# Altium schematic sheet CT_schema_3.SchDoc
size 309 x 321 mm
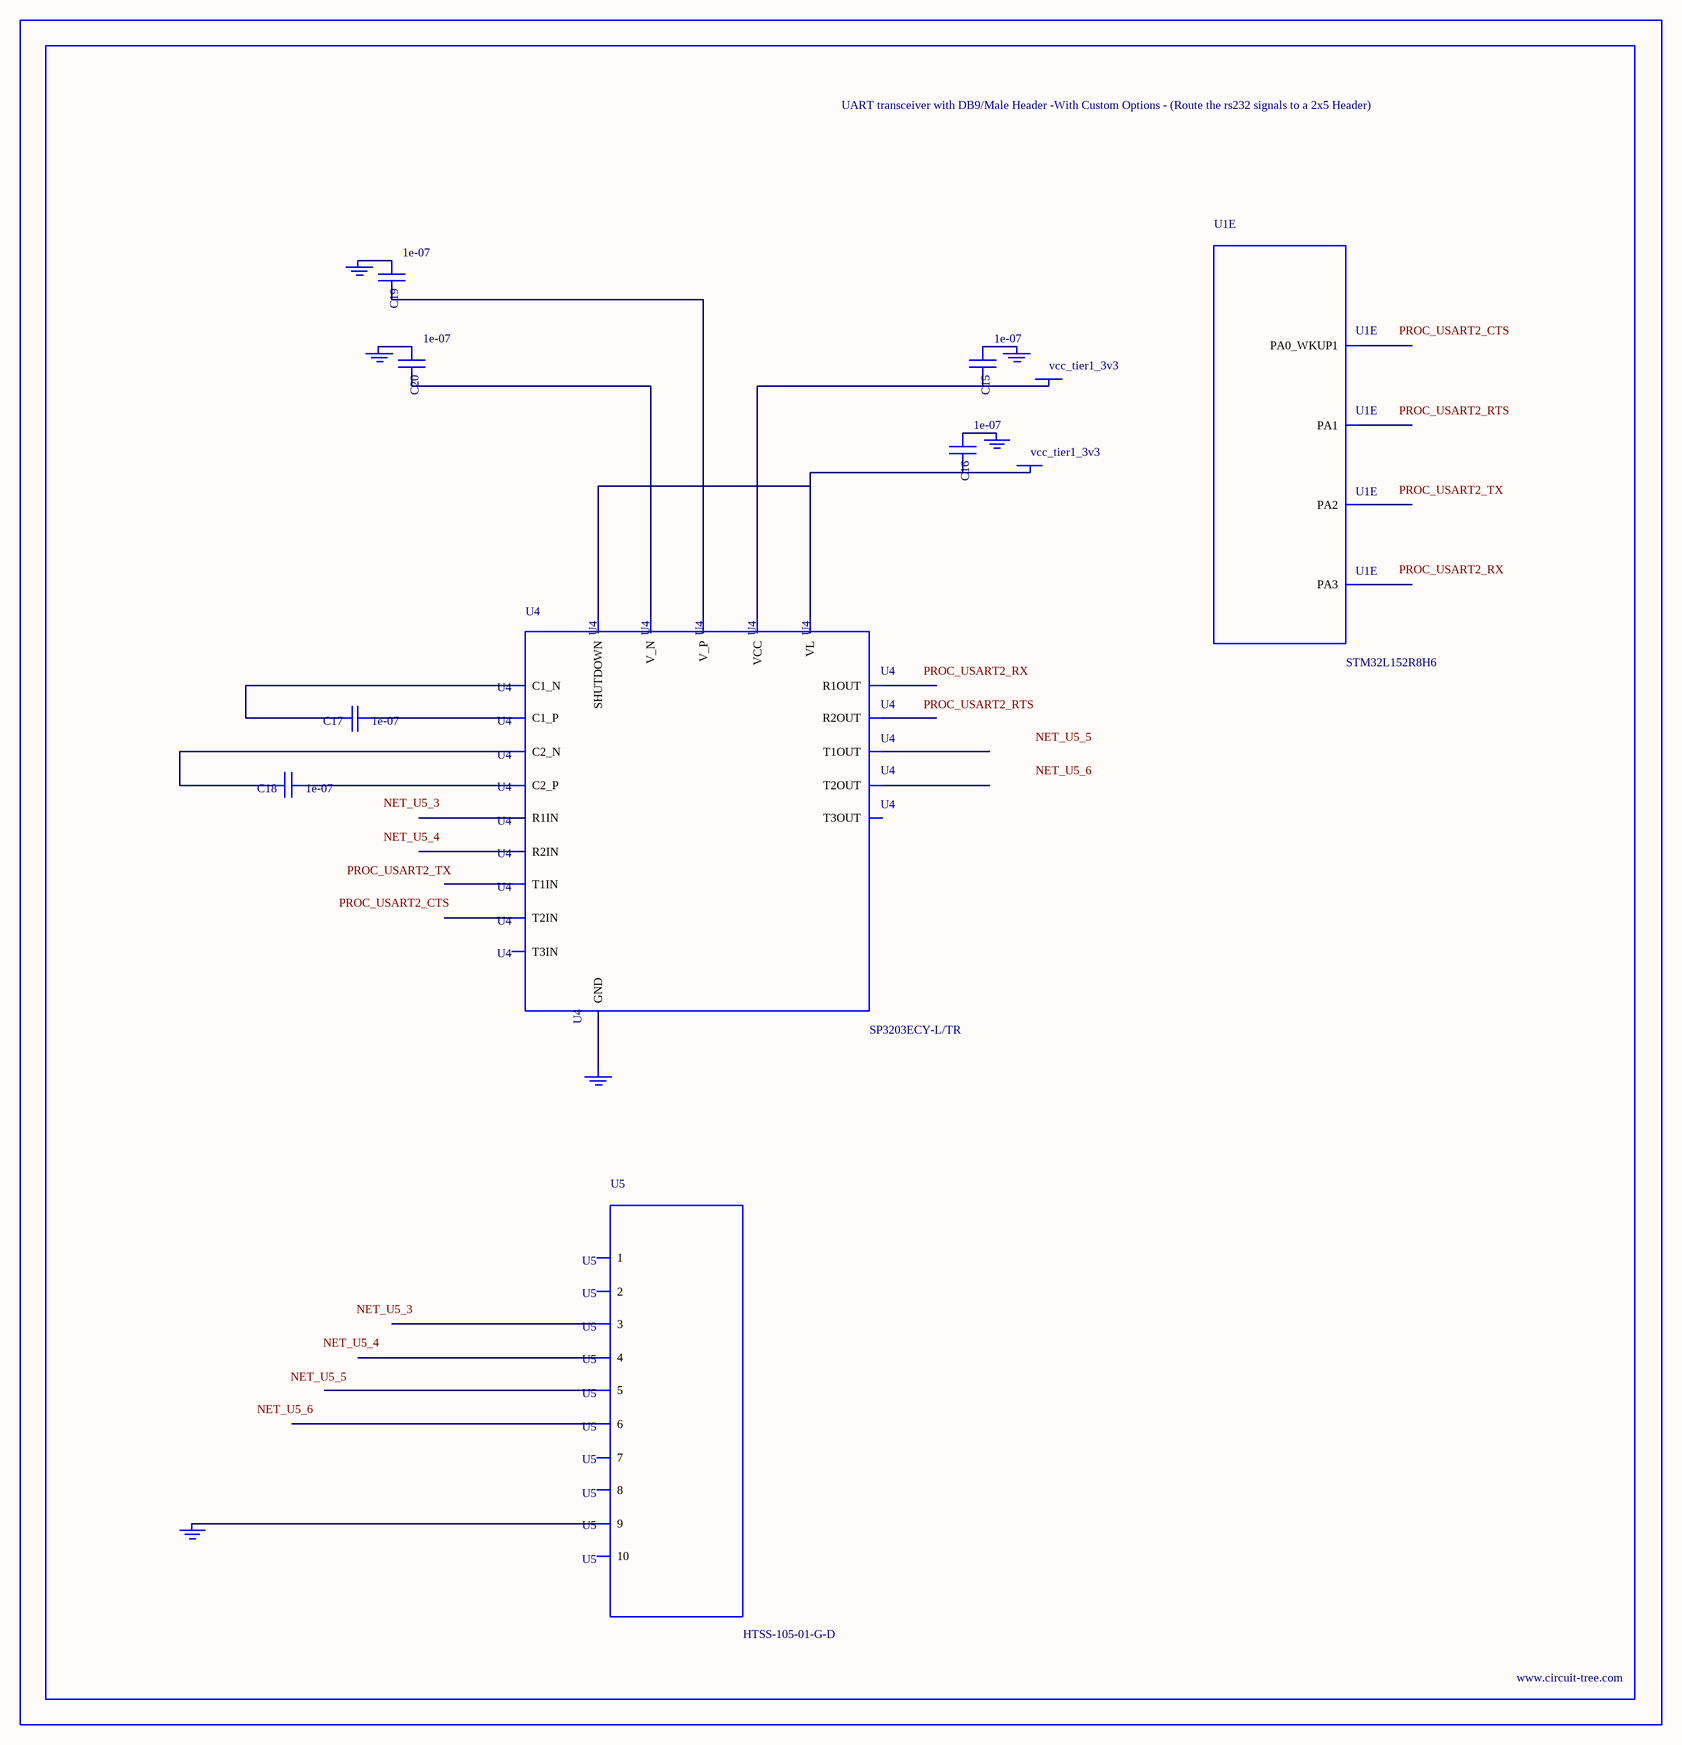
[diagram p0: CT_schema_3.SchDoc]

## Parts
BORDER2  (no value)
C15  1e-07  [C0402]
C16  1e-07  [C0402]
C17  1e-07  [C0402]
C18  1e-07  [C0402]
C19  1e-07  [C0402]
C20  1e-07  [C0402]
GND_INSTANCE_2_0  (no value)
GND_INSTANCE_2_1  (no value)
GND_INSTANCE_2_2  (no value)
GND_INSTANCE_2_3  (no value)
GND_INSTANCE_2_4  (no value)
GND_INSTANCE_2_5  (no value)
POWER_INSTANCE_2_0  vcc_tier1_3v3
POWER_INSTANCE_2_1  vcc_tier1_3v3
U1  STM32L152R8H6  [TFBGA64]  (part E of 6)
U4  SP3203ECY-L/TR  [TSSOP20-I]
U5  HTSS-105-01-G-D  [HTSS-105-01-G-D]

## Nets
NetC15_1: C15.1 GND_INSTANCE_2_3.0(GND)
NetC15_2: C15.2 POWER_INSTANCE_2_1.0(PWR) U4.19(VCC)
NetC16_1: C16.1 GND_INSTANCE_2_2.0(GND)
NetC16_2: C16.2 POWER_INSTANCE_2_0.0(PWR) U4.12(VL) U4.20(SHUTDOWN)
NetC17_1: C17.1 U4.1(C1_P)
NetC17_2: C17.2 U4.3(C1_N)
NetC18_1: C18.1 U4.4(C2_P)
NetC18_2: C18.2 U4.5(C2_N)
NetC19_1: C19.1 GND_INSTANCE_2_0.0(GND)
NetC19_2: C19.2 U4.2(V_P)
NetC20_1: C20.1 GND_INSTANCE_2_1.0(GND)
NetC20_2: C20.2 U4.6(V_N)
NetGND_INSTANCE_2_4_0: GND_INSTANCE_2_4.0(GND) U4.18(GND)
NetGND_INSTANCE_2_5_0: GND_INSTANCE_2_5.0(GND) U5.9

Not connected (* = marked no-connect by the designer): U1 F3(PA2) G2(PA0_WKUP1) G3(PA3) H2(PA1); U4 7(T1IN) 8(T2IN) 9(T3IN) 10(R2OUT) 11(R1OUT) 13(R2IN) 14(R1IN) 15(T3OUT) 16(T2OUT) 17(T1OUT); U5 1 2 3 4 5 6 7 8 10

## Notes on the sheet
- Labels drawn without touching a wire or pin: NET_U5_3, NET_U5_4, NET_U5_5, NET_U5_6, PROC_USART2_CTS, PROC_USART2_RTS, PROC_USART2_RX, PROC_USART2_TX

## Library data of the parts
BORDER2 = BORDER_PAGE2
C15-C20 = C0402C104K3RACTU
GND_INSTANCE_2_0-GND_INSTANCE_2_5 = GND
POWER_INSTANCE_2_0 POWER_INSTANCE_2_1 = PWR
